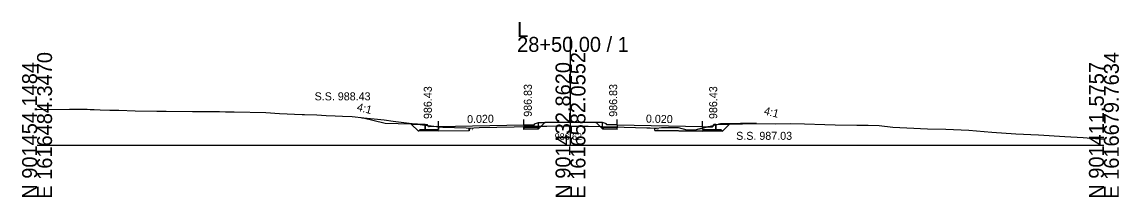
# Model space of a CAD drawing. Extents: x 1009 to 7438, y -1586 to 7964.
# Drawn here: x 2032.1 to 2237.7, y 6414 to 6446.9 of the extents above; entities that cross this region are included whole.
import ezdxf

# ---------------------------------------------------------------- set-up
doc = ezdxf.new("R2010")
doc.units = 0
for name, color, linetype in [('Exist Cross Section Cell', 7, 'Continuous'), ('Exist XS Center Line Elevation Label', 7, 'Continuous'), ('Exist XS Ground Line', 7, 'Continuous'), ('Prop XS Dump Level', 7, 'Continuous'), ('Prop XS Earthwork Shape', 7, 'Continuous'), ('Prop XS EOT Tick Mark', 7, 'Continuous'), ('Prop XS Finish Grade', 7, 'Continuous'), ('Prop XS Finish Grade CurbGutter', 7, 'Continuous'), ('Prop XS Finish Grade Earthwork', 7, 'Continuous'), ('Prop XS Finish Grade Pavement', 7, 'Continuous'), ('Prop XS Hydro Elevations', 7, 'Continuous'), ('Prop XS Pvmt Edge Slope', 7, 'Continuous'), ('Prop XS SE Text', 7, 'Continuous'), ('Prop XS Side Slope Text', 7, 'Continuous'), ('Prop XS SS Elevation Text', 7, 'Continuous'), ('Prop XS Subgrade CurbGutter', 7, 'Continuous'), ('Prop XS Subgrade Earthwork', 7, 'Continuous')]:
    doc.layers.add(name, color=color, linetype=linetype)

msp = doc.modelspace()

# ---------------------------------------------------------------- linework, layer by layer
at = {"layer": 'Exist Cross Section Cell'}
for p, q in [((2134.89, 6423.73), (2134.89, 6444.05)), ((2034.89, 6423.73), (2134.89, 6423.73)), ((2134.89, 6423.73), (2234.89, 6423.73))]:
    msp.add_line(p, q, dxfattribs=at)
at = {"layer": 'Exist XS Ground Line'}
for p, q in [((2034.89, 6430.44), (2040.95, 6430.49)), ((2040.95, 6430.49), (2041.98, 6430.5)), ((2041.98, 6430.5), (2042.7, 6430.49)), ((2042.7, 6430.49), (2043.21, 6430.49)), ((2043.21, 6430.49), (2043.8, 6430.49)), ((2043.8, 6430.49), (2044.27, 6430.48)), ((2044.27, 6430.48), (2044.85, 6430.46)), ((2044.85, 6430.46), (2045.59, 6430.43)), ((2045.59, 6430.43), (2046.71, 6430.38)), ((2046.71, 6430.38), (2048.55, 6430.34)), ((2048.55, 6430.34), (2050.21, 6430.31)), ((2050.21, 6430.31), (2053.26, 6430.22)), ((2053.26, 6430.22), (2057.33, 6430.11)), ((2057.33, 6430.11), (2059.09, 6430.11)), ((2059.09, 6430.11), (2064.05, 6430.08)), ((2064.05, 6430.08), (2067.73, 6430.04)), ((2067.73, 6430.04), (2069.1, 6430.06)), ((2069.1, 6430.06), (2070.19, 6430.03)), ((2070.19, 6430.03), (2071.83, 6430.01)), ((2071.83, 6430.01), (2077.78, 6429.89)), ((2077.78, 6429.89), (2080.36, 6429.72)), ((2080.36, 6429.72), (2084.58, 6429.52)), ((2084.58, 6429.52), (2085.04, 6429.51)), ((2085.04, 6429.51), (2087.36, 6429.44)), ((2087.36, 6429.44), (2089.07, 6429.35)), ((2089.07, 6429.35), (2090.76, 6429.25)), ((2090.76, 6429.25), (2092.16, 6429.2)), ((2092.16, 6429.2), (2093.93, 6429.11)), ((2093.93, 6429.11), (2096.15, 6428.86)), ((2096.15, 6428.86), (2098.69, 6428.64)), ((2098.69, 6428.64), (2099.96, 6428.52)), ((2099.96, 6428.52), (2101.63, 6428.28)), ((2101.63, 6428.28), (2103.62, 6427.99)), ((2103.62, 6427.99), (2106.7, 6427.63)), ((2106.7, 6427.63), (2107.55, 6427.53)), ((2161.15, 6427.34), (2162.06, 6427.58)), ((2162.06, 6427.58), (2163, 6427.73)), ((2163, 6427.73), (2164.25, 6427.73)), ((2164.25, 6427.73), (2166.78, 6427.82)), ((2166.78, 6427.82), (2173.26, 6427.75)), ((2173.26, 6427.75), (2176.22, 6427.82)), ((2176.22, 6427.82), (2178.74, 6427.76)), ((2178.74, 6427.76), (2182.58, 6427.63)), ((2182.58, 6427.63), (2184.51, 6427.57)), ((2184.51, 6427.57), (2188.59, 6427.53)), ((2107.55, 6427.53), (2108.74, 6427.39)), ((2108.74, 6427.39), (2109.8, 6427.26)), ((2109.8, 6427.26), (2110.49, 6427.18)), ((2110.49, 6427.18), (2110.95, 6427.13)), ((2110.95, 6427.13), (2115.31, 6427.01)), ((2115.31, 6427.01), (2115.89, 6426.96)), ((2115.89, 6426.96), (2116.74, 6427.02)), ((2116.74, 6427.02), (2117.8, 6427.04)), ((2117.8, 6427.04), (2127.62, 6427.28)), ((2127.62, 6427.28), (2128.2, 6427.28)), ((2128.2, 6427.28), (2132.74, 6427.38)), ((2132.74, 6427.38), (2134.89, 6427.35)), ((2134.89, 6427.35), (2137.57, 6427.33)), ((2137.57, 6427.33), (2138.19, 6427.32)), ((2138.19, 6427.32), (2140.73, 6427.25)), ((2140.73, 6427.25), (2149.23, 6427.03)), ((2149.23, 6427.03), (2149.84, 6427.01)), ((2149.84, 6427.01), (2150.7, 6426.96)), ((2150.7, 6426.96), (2151.04, 6426.96)), ((2151.04, 6426.96), (2151.98, 6427.08)), ((2151.98, 6427.08), (2152.44, 6427.07)), ((2152.44, 6427.07), (2152.98, 6427.07)), ((2152.98, 6427.07), (2153.56, 6427.1)), ((2153.56, 6427.1), (2155.07, 6427.07)), ((2155.07, 6427.07), (2156.68, 6426.65)), ((2156.68, 6426.65), (2157.22, 6426.62)), ((2157.22, 6426.62), (2157.86, 6426.63)), ((2157.86, 6426.63), (2158.24, 6426.66)), ((2158.24, 6426.66), (2161.15, 6427.34)), ((2188.59, 6427.53), (2190.67, 6427.49)), ((2190.67, 6427.49), (2192.77, 6427.43)), ((2192.77, 6427.43), (2195.29, 6427.15)), ((2195.29, 6427.15), (2197.96, 6427.01)), ((2197.96, 6427.01), (2201.83, 6426.85)), ((2201.83, 6426.85), (2205.25, 6426.74)), ((2205.25, 6426.74), (2209.55, 6426.56)), ((2209.55, 6426.56), (2213.86, 6426.19)), ((2213.86, 6426.19), (2218.38, 6425.86)), ((2218.38, 6425.86), (2222.66, 6425.68)), ((2222.66, 6425.68), (2227.59, 6425.39)), ((2227.59, 6425.39), (2231.03, 6425.18)), ((2231.03, 6425.18), (2234.89, 6424.87))]:
    msp.add_line(p, q, dxfattribs=at)
at = {"layer": 'Prop XS Dump Level'}
for p, q in [((2110.14, 6427.28), (2126.14, 6427.6)), ((2110.14, 6427.28), (2126.14, 6427.6)), ((2143.64, 6427.6), (2159.64, 6427.28)), ((2143.64, 6427.6), (2159.64, 6427.28))]:
    msp.add_line(p, q, dxfattribs=at)
at = {"layer": 'Prop XS Earthwork Shape'}
for points in [[(2100.14, 6427.81), (2095.77, 6428.91), (2096.15, 6428.86), (2098.69, 6428.64), (2099.96, 6428.52), (2101.63, 6428.28), (2103.62, 6427.99), (2106.21, 6427.69), (2105.05, 6427.71)], [(2106.39, 6426.37), (2105.05, 6427.71), (2106.21, 6427.69), (2106.7, 6427.63), (2107.55, 6427.53), (2107.64, 6427.52), (2107.64, 6426.65), (2106.64, 6426.63)], [(2129.38, 6427.31), (2132.74, 6427.38), (2134.89, 6427.35), (2137.57, 6427.33), (2138.19, 6427.32), (2140.46, 6427.26), (2139.72, 6428), (2139.67, 6428), (2134.89, 6428.1), (2130.12, 6428), (2130.07, 6428)], [(2160.61, 6427.22), (2161.39, 6427.17), (2161.52, 6427.19), (2161.61, 6427.29), (2161.66, 6427.47), (2162.06, 6427.58), (2162.14, 6427.59), (2162.14, 6426.65), (2159.64, 6426.7), (2159.64, 6426.99)], [(2162.62, 6427.67), (2164.73, 6427.71), (2163.39, 6426.37), (2163.14, 6426.63), (2162.14, 6426.65), (2162.14, 6427.59)], [(2162.62, 6427.67), (2164.73, 6427.71), (2168.9, 6427.8), (2166.78, 6427.82), (2164.25, 6427.73), (2163, 6427.73)], [(2168.9, 6427.8), (2169.74, 6427.79), (2169.64, 6427.81)], [(2115.89, 6426.47), (2110.14, 6426.36), (2110.14, 6426.45), (2106.39, 6426.37), (2106.64, 6426.63), (2107.64, 6426.65), (2110.14, 6426.7), (2110.14, 6427.22), (2110.49, 6427.18), (2110.95, 6427.13), (2115.31, 6427.01), (2115.89, 6426.96)], [(2108.39, 6427.17), (2108.27, 6427.19), (2108.18, 6427.29), (2108.13, 6427.46), (2107.64, 6427.52), (2107.64, 6426.65), (2110.14, 6426.7), (2110.14, 6427.22), (2109.85, 6427.26)], [(2108.39, 6427.17), (2108.27, 6427.19), (2108.18, 6427.29), (2108.13, 6427.46), (2108.74, 6427.39), (2109.8, 6427.26), (2109.85, 6427.26)], [(2126.14, 6427.02), (2127.64, 6427.05), (2128.64, 6427.07), (2128.89, 6427.07), (2128.89, 6427.3), (2128.2, 6427.28), (2127.62, 6427.28), (2126.14, 6427.24)], [(2126.14, 6426.77), (2128.89, 6426.82), (2128.64, 6427.07), (2127.64, 6427.05), (2126.14, 6427.02)], [(2128.89, 6427.3), (2129.38, 6427.31), (2128.89, 6426.82), (2128.64, 6427.07), (2128.89, 6427.07)], [(2140.46, 6427.26), (2140.73, 6427.25), (2140.89, 6427.25), (2140.89, 6427.07), (2141.14, 6427.07), (2140.9, 6426.82)], [(2140.89, 6427.25), (2143.64, 6427.18), (2143.64, 6427.02), (2142.14, 6427.05), (2141.14, 6427.07), (2140.89, 6427.07)], [(2143.64, 6426.77), (2143.64, 6427.02), (2142.14, 6427.05), (2141.14, 6427.07), (2140.9, 6426.82)], [(2159.64, 6426.99), (2159.64, 6426.7), (2162.14, 6426.65), (2163.14, 6426.63), (2163.39, 6426.37), (2159.64, 6426.45), (2159.64, 6426.36), (2150.7, 6426.54), (2150.7, 6426.96), (2151.04, 6426.96), (2151.98, 6427.08), (2152.44, 6427.07), (2152.98, 6427.07), (2153.56, 6427.1), (2155.07, 6427.07), (2156.68, 6426.65), (2157.22, 6426.62), (2157.86, 6426.63), (2158.24, 6426.66)], [(2160.61, 6427.22), (2161.15, 6427.34), (2161.66, 6427.47), (2161.61, 6427.29), (2161.52, 6427.19), (2161.39, 6427.17)]]:
    msp.add_lwpolyline(points, close=True, dxfattribs=at)
at = {"layer": 'Prop XS EOT Tick Mark'}
for p, q in [((2110.14, 6427.28), (2110.14, 6428.28)), ((2126.14, 6427.6), (2126.14, 6428.6)), ((2143.64, 6427.6), (2143.64, 6428.6)), ((2159.64, 6427.28), (2159.64, 6428.28))]:
    msp.add_line(p, q, dxfattribs=at)
at = {"layer": 'Prop XS Finish Grade'}
for p, q in [((2107.64, 6427.66), (2105.05, 6427.71)), ((2128.89, 6427.98), (2130.12, 6428)), ((2140.89, 6427.98), (2139.67, 6428)), ((2162.14, 6427.66), (2164.73, 6427.71))]:
    msp.add_line(p, q, dxfattribs=at)
at = {"layer": 'Prop XS Finish Grade CurbGutter'}
for p, q in [((2107.64, 6427.66), (2107.89, 6427.66)), ((2107.89, 6427.66), (2108.02, 6427.63)), ((2108.11, 6427.54), (2108.02, 6427.63)), ((2126.14, 6427.6), (2126.89, 6427.58)), ((2126.14, 6427.6), (2128.14, 6427.56)), ((2128.14, 6427.73), (2128.89, 6427.98)), ((2128.14, 6427.56), (2128.14, 6427.73)), ((2141.64, 6427.73), (2140.89, 6427.98)), ((2141.64, 6427.56), (2141.64, 6427.73)), ((2143.64, 6427.6), (2141.64, 6427.56)), ((2143.64, 6427.6), (2142.89, 6427.58)), ((2161.68, 6427.54), (2161.77, 6427.63)), ((2161.89, 6427.66), (2161.77, 6427.63)), ((2162.14, 6427.66), (2161.89, 6427.66)), ((2108.18, 6427.29), (2108.11, 6427.54)), ((2108.27, 6427.19), (2108.18, 6427.29)), ((2108.39, 6427.17), (2108.27, 6427.19)), ((2110.14, 6427.28), (2108.39, 6427.17)), ((2159.64, 6427.28), (2161.39, 6427.17)), ((2161.39, 6427.17), (2161.52, 6427.19)), ((2161.52, 6427.19), (2161.61, 6427.29)), ((2161.61, 6427.29), (2161.68, 6427.54))]:
    msp.add_line(p, q, dxfattribs=at)
at = {"layer": 'Prop XS Finish Grade Earthwork'}
for p, q in [((2100.14, 6427.81), (2095.77, 6428.91)), ((2105.05, 6427.71), (2100.14, 6427.81)), ((2130.12, 6428), (2134.89, 6428.1)), ((2134.89, 6428.1), (2139.67, 6428)), ((2164.73, 6427.71), (2169.64, 6427.81)), ((2169.64, 6427.81), (2169.74, 6427.79))]:
    msp.add_line(p, q, dxfattribs=at)
at = {"layer": 'Prop XS Finish Grade Pavement'}
for p, q in [((2110.14, 6427.28), (2126.14, 6427.6)), ((2143.64, 6427.6), (2159.64, 6427.28))]:
    msp.add_line(p, q, dxfattribs=at)
at = {"layer": 'Prop XS Pvmt Edge Slope'}
for p, q in [((2106.64, 6426.63), (2106.39, 6426.37)), ((2107.64, 6426.65), (2106.64, 6426.63)), ((2127.64, 6427.05), (2128.64, 6427.07)), ((2127.64, 6427.05), (2128.89, 6427.07)), ((2128.64, 6427.07), (2128.89, 6426.82)), ((2142.14, 6427.05), (2140.89, 6427.07)), ((2141.14, 6427.07), (2140.9, 6426.82)), ((2142.14, 6427.05), (2141.14, 6427.07)), ((2162.14, 6426.65), (2163.14, 6426.63)), ((2163.14, 6426.63), (2163.39, 6426.37))]:
    msp.add_line(p, q, dxfattribs=at)
at = {"layer": 'Prop XS Subgrade CurbGutter'}
for p, q in [((2107.64, 6426.65), (2107.64, 6427.66)), ((2126.14, 6427.6), (2126.14, 6427.02)), ((2128.89, 6427.07), (2128.89, 6427.98)), ((2140.89, 6427.07), (2140.89, 6427.98)), ((2143.64, 6427.6), (2143.64, 6427.02)), ((2162.14, 6426.65), (2162.14, 6427.66)), ((2110.14, 6426.7), (2107.64, 6426.65)), ((2110.14, 6427.28), (2110.14, 6426.7)), ((2126.14, 6427.02), (2127.64, 6427.05)), ((2143.64, 6427.02), (2142.14, 6427.05)), ((2159.64, 6427.28), (2159.64, 6426.7)), ((2159.64, 6426.7), (2162.14, 6426.65))]:
    msp.add_line(p, q, dxfattribs=at)
at = {"layer": 'Prop XS Subgrade Earthwork'}
for p, q in [((2106.39, 6426.37), (2105.05, 6427.71)), ((2128.89, 6426.82), (2130.07, 6428)), ((2140.9, 6426.82), (2139.72, 6428)), ((2163.39, 6426.37), (2164.73, 6427.71)), ((2110.14, 6426.45), (2106.39, 6426.37)), ((2115.89, 6426.47), (2110.14, 6426.36)), ((2110.14, 6426.36), (2110.14, 6426.45)), ((2115.89, 6426.47), (2115.89, 6426.96)), ((2126.14, 6426.68), (2126.14, 6427.24)), ((2126.14, 6426.77), (2128.89, 6426.82)), ((2126.14, 6426.68), (2126.14, 6426.77)), ((2143.64, 6426.77), (2140.9, 6426.82)), ((2143.64, 6426.68), (2143.64, 6427.18)), ((2143.64, 6426.68), (2143.64, 6426.77)), ((2150.7, 6426.54), (2150.7, 6426.96)), ((2150.7, 6426.54), (2159.64, 6426.36)), ((2159.64, 6426.36), (2159.64, 6426.45)), ((2159.64, 6426.45), (2163.39, 6426.37))]:
    msp.add_line(p, q, dxfattribs=at)

# ---------------------------------------------------------------- texts
at = {"layer": 'Exist Cross Section Cell'}
for s, p in [('L', (2124.89, 6444.05)), ('28+50.00 / 1', (2124.89, 6441.25))]:
    msp.add_text(s, height=2.8, dxfattribs=at).set_placement(p)
for s, p in [('E 1616484.3470', (2037.69, 6413.73)), ('E 1616582.0552', (2137.69, 6413.73)), ('E 1616679.7634', (2237.69, 6413.73)), ('N 901454.1484', (2034.89, 6413.73)), ('N 901432.8620', (2134.89, 6413.73)), ('N 901411.5757', (2234.89, 6413.73))]:
    msp.add_text(s, height=2.8, rotation=90, dxfattribs=at).set_placement(p)
at = {"layer": 'Exist XS Center Line Elevation Label'}
msp.add_text('986.62', height=1.25, dxfattribs=at).set_placement((2131.93, 6424.73))
at = {"layer": 'Prop XS Dump Level'}
for p in [(2115.89, 6426.66), (2115.89, 6426.66), (2150.7, 6426.66), (2150.7, 6426.66)]:
    msp.add_text('Eop', height=0.3, dxfattribs=at).set_placement(p)
at = {"layer": 'Prop XS Hydro Elevations'}
for s, p in [('986.43', (2108.89, 6428.66)), ('986.83', (2127.64, 6429.08)), ('986.83', (2143.64, 6429.08)), ('986.43', (2162.39, 6428.66))]:
    msp.add_text(s, height=1.5, rotation=90, dxfattribs=at).set_placement(p)
at = {"layer": 'Prop XS SE Text'}
for rotation, p in [(1.1458, (2115.52, 6427.88)), (358.8542, (2149.02, 6427.99))]:
    msp.add_text('0.020', height=1.5, rotation=rotation, dxfattribs=at).set_placement(p)
at = {"layer": 'Prop XS Side Slope Text'}
for p in [(2094.74, 6430.25), (2171.04, 6429.55)]:
    msp.add_text('4:1', height=1.5, rotation=345.9638, dxfattribs=at).set_placement(p)
at = {"layer": 'Prop XS SS Elevation Text'}
for s, p in [('S.S. 988.43', (2086.92, 6432.16)), ('S.S. 987.03', (2165.95, 6424.76))]:
    msp.add_text(s, height=1.5, dxfattribs=at).set_placement(p)

doc.saveas('drawing.dxf')
